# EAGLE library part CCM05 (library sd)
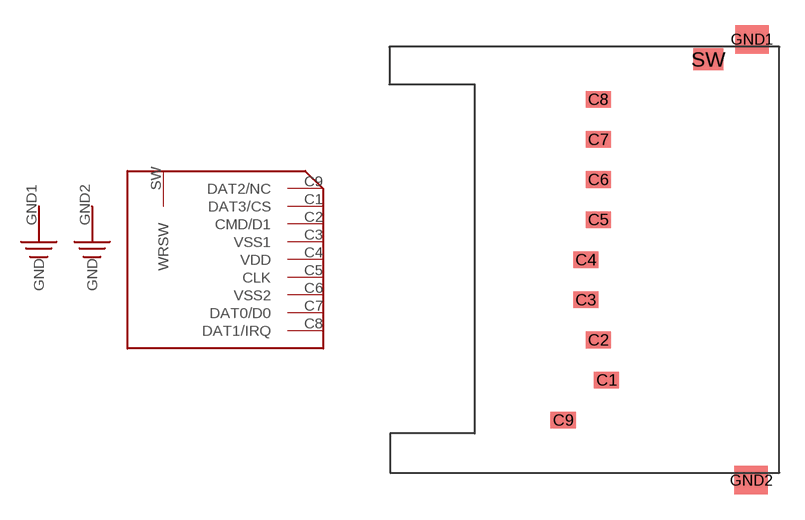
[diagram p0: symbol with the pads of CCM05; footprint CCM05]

Designator prefix -; gates SDCARD=SD/MMC GND1=GND GND2=GND

## CCM05  [CCM05]
C1  SDCARD:DAT3/CS
C2  SDCARD:CMD/D1
C3  SDCARD:VSS1
C4  SDCARD:VDD
C5  SDCARD:CLK
C6  SDCARD:VSS2
C7  SDCARD:DAT0/D0
C8  SDCARD:DAT1/IRQ
C9  SDCARD:DAT2/NC
GND1  GND1:GND
GND2  GND2:GND
SW  SDCARD:WRSW

## Footprint CCM05 (pad centres in mm)
smd 1.5 x 1: C1 1.25,-7.2; C2 0.75,-4.8; C3 0,-2.4; C4 0,0; C5 0.75,2.4; C6 0.75,4.8; C7 0.75,7.2; C8 0.75,9.6; C9 -1.35,-9.6
smd 2 x 1.7: GND1 9.95,13.2; GND2 9.9,-13.2
smd 1.8 x 1.3: SW 7.35,12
